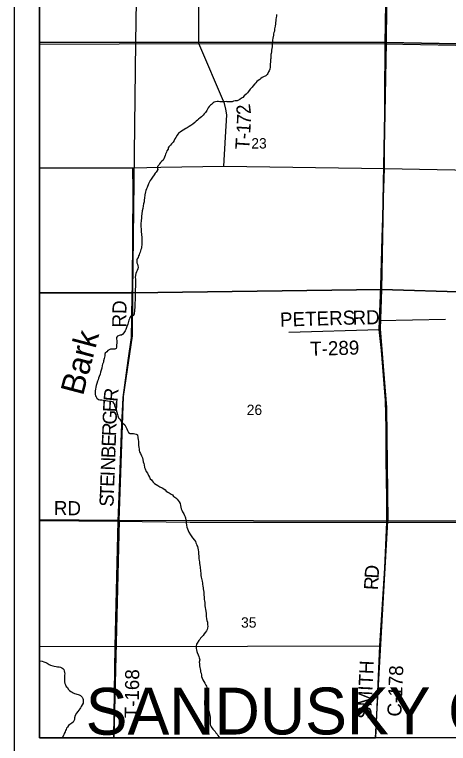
# Model space of a CAD drawing. Extents: x 0 to 34, y 0 to 22.
# Drawn here: x 23.417 to 25.169, y 14.078 to 17.024 of the extents above; entities that cross this region are included whole.
import ezdxf

# ---------------------------------------------------------------- set-up
doc = ezdxf.new("R2010")
doc.units = 0
for name, color, linetype in [('GM_X_County_Road', 7, 'Continuous'), ('GM_X_County_Road_Text', 7, 'Continuous'), ('GM_X_County_Text', 7, 'Continuous'), ('GM_X_Minor_River', 7, 'Continuous'), ('GM_X_Minor_River_Text', 7, 'Continuous'), ('GM_X_Section', 7, 'Continuous'), ('GM_X_Section_Text', 7, 'Continuous'), ('GM_X_Township_Road', 7, 'Continuous'), ('GM_X_Township_Road_Text', 7, 'Continuous'), ('SH_Data', 7, 'Continuous')]:
    doc.layers.add(name, color=color, linetype=linetype)

msp = doc.modelspace()

# ---------------------------------------------------------------- linework, layer by layer
at = {"layer": 'GM_X_County_Road'}
msp.add_line((23.5167, 14.9786), (23.8356, 14.976), dxfattribs=at)
for points in [[(24.9139, 16.9052), (24.9179, 17.1535), (24.9168, 17.4836), (24.9237, 17.8223), (24.9385, 18.1961), (24.9527, 18.4155)], [(24.9115, 16.4019), (24.9123, 16.6864), (24.9139, 16.9052)], [(24.007, 16.4066), (24.2617, 16.4112), (24.9115, 16.4019), (25.9746, 16.3822)], [(23.5167, 16.4046), (23.8475, 16.4049), (23.8949, 16.4045), (24.007, 16.4066)], [(24.9205, 14.9723), (24.9198, 15.0684), (24.9178, 15.2261), (24.9171, 15.3511), (24.9151, 15.464), (24.8982, 15.6659), (24.8893, 15.7512), (24.8908, 15.788), (24.8963, 15.9243), (24.901, 16.1233), (24.9115, 16.4019)], [(23.8356, 14.976), (24.1256, 14.9725), (24.4361, 14.9725), (24.6013, 14.9725), (24.9205, 14.9723), (25.4304, 14.971), (25.8247, 14.9796), (25.8949, 14.9801), (25.9099, 14.9816), (25.9117, 14.9818), (25.9196, 14.987)], [(24.8753, 14.1), (24.892, 14.4729), (24.9118, 14.7856), (24.9205, 14.9723)]]:
    msp.add_lwpolyline(points, dxfattribs=at)
at = {"layer": 'GM_X_Minor_River'}
for points in [[(24.475, 17.0244), (24.4742, 17.0179), (24.4734, 17.0122), (24.4725, 17.0035), (24.4721, 16.9982), (24.4709, 16.9918), (24.47, 16.9861), (24.4692, 16.9774), (24.4676, 16.9721), (24.4672, 16.9668), (24.4659, 16.9569), (24.4643, 16.952), (24.4631, 16.9459), (24.4619, 16.941), (24.4603, 16.9281), (24.4587, 16.9209), (24.4578, 16.9156), (24.4574, 16.908), (24.4569, 16.9031), (24.4569, 16.8986), (24.4565, 16.8936), (24.4556, 16.8864), (24.4548, 16.88), (24.454, 16.8732), (24.4531, 16.8671), (24.4523, 16.8622), (24.4522, 16.8538), (24.4514, 16.847), (24.4509, 16.8417), (24.4504, 16.8311), (24.4496, 16.8254), (24.4491, 16.8163), (24.4487, 16.811), (24.4475, 16.8034), (24.4451, 16.797), (24.4428, 16.792), (24.4397, 16.7864)], [(24.4397, 16.7864), (24.4366, 16.7815), (24.4312, 16.777), (24.4225, 16.7721), (24.4171, 16.7695), (24.4118, 16.7654), (24.4068, 16.7617), (24.4011, 16.7579), (24.3957, 16.7531), (24.3907, 16.7482), (24.3869, 16.7437), (24.3792, 16.735), (24.3761, 16.7301), (24.3684, 16.7219), (24.3615, 16.7128), (24.3572, 16.7079), (24.3515, 16.7019), (24.3442, 16.6952), (24.3381, 16.6892), (24.3335, 16.6862), (24.3266, 16.6802), (24.3212, 16.6776), (24.3159, 16.6757), (24.3072, 16.6747), (24.3007, 16.674), (24.2958, 16.6718), (24.2901, 16.6714), (24.2817, 16.6712), (24.2756, 16.6712), (24.2707, 16.672), (24.2582, 16.6718), (24.251, 16.6715), (24.2461, 16.6715), (24.2408, 16.6724), (24.2351, 16.672), (24.2279, 16.6714), (24.2229, 16.6703), (24.2183, 16.6669), (24.2125, 16.6598), (24.208, 16.6575), (24.203, 16.6523), (24.1991, 16.6466), (24.1937, 16.6364), (24.1872, 16.6285), (24.1818, 16.6225), (24.1779, 16.6176), (24.1722, 16.6112), (24.1664, 16.6063), (24.1599, 16.6011), (24.1553, 16.597), (24.15, 16.5925), (24.1442, 16.5872), (24.1365, 16.5805), (24.1285, 16.5756), (24.122, 16.5715), (24.114, 16.5655), (24.109, 16.5633), (24.0976, 16.5566), (24.0915, 16.5529), (24.085, 16.5488), (24.0804, 16.5465), (24.0765, 16.5409), (24.0738, 16.5364), (24.0684, 16.5277), (24.0646, 16.5213), (24.0614, 16.5148), (24.0576, 16.5084), (24.0503, 16.5017), (24.0461, 16.4964), (24.0399, 16.49), (24.0376, 16.4847), (24.0368, 16.4798), (24.0321, 16.473), (24.0302, 16.4681), (24.0263, 16.4598), (24.0251, 16.4549), (24.0224, 16.4473), (24.02, 16.4413), (24.0162, 16.4352), (24.0116, 16.4315), (24.0062, 16.4255), (24.0016, 16.421), (23.9989, 16.4153), (23.9946, 16.4104), (23.9938, 16.4024), (23.9956, 16.3971), (23.9914, 16.3915), (23.9883, 16.3869), (23.9845, 16.3824), (23.9806, 16.3764), (23.9733, 16.367), (23.969, 16.3591), (23.9644, 16.353), (23.9613, 16.3481), (23.9574, 16.3398), (23.9523, 16.3251), (23.9496, 16.3194), (23.9473, 16.3126), (23.9457, 16.3069), (23.9433, 16.2956), (23.9432, 16.291)], [(23.9432, 16.291), (23.942, 16.2865), (23.9407, 16.2717), (23.9395, 16.2668), (23.9379, 16.2592), (23.9363, 16.2512), (23.9343, 16.2406), (23.9323, 16.2304), (23.9306, 16.2186), (23.9294, 16.2088), (23.9289, 16.2038), (23.9284, 16.1894), (23.9272, 16.1807), (23.9267, 16.1705), (23.9266, 16.1659), (23.9273, 16.1576), (23.9276, 16.153), (23.9279, 16.1446), (23.929, 16.1378), (23.9297, 16.1325), (23.9303, 16.126), (23.931, 16.1165), (23.9313, 16.1101), (23.9312, 16.0991), (23.9307, 16.0937), (23.9299, 16.0858), (23.9287, 16.0797), (23.9267, 16.074), (23.9255, 16.0695), (23.9236, 16.0635), (23.9216, 16.0582), (23.92, 16.0529), (23.9173, 16.0483), (23.9153, 16.0415), (23.9123, 16.0366), (23.9107, 16.0321), (23.9099, 16.0275), (23.9109, 16.0199), (23.9131, 16.015), (23.9146, 16.0085), (23.9153, 16.0024), (23.9148, 15.9967), (23.9113, 15.9892), (23.9086, 15.9843), (23.907, 15.9771), (23.9047, 15.9706), (23.9038, 15.9615), (23.9045, 15.9558), (23.9056, 15.9494), (23.9051, 15.9399), (23.905, 15.935), (23.9054, 15.93), (23.9045, 15.9221), (23.9044, 15.9152), (23.904, 15.9099), (23.9043, 15.9019), (23.9041, 15.8883), (23.9036, 15.8792), (23.9032, 15.8697), (23.903, 15.8591), (23.9026, 15.8503), (23.9025, 15.8458), (23.902, 15.839), (23.9012, 15.8314), (23.9007, 15.8242), (23.9003, 15.8185), (23.8999, 15.8139), (23.8975, 15.8071), (23.8914, 15.8049), (23.8869, 15.8049), (23.8826, 15.8001), (23.8814, 15.7944), (23.8783, 15.7891), (23.8768, 15.7838), (23.8756, 15.7777), (23.8736, 15.7728), (23.8705, 15.7637), (23.8693, 15.7592), (23.8654, 15.7505), (23.8631, 15.7456), (23.8576, 15.7369), (23.8534, 15.732), (23.8488, 15.7287), (23.8435, 15.728), (23.8389, 15.7269), (23.8325, 15.7235), (23.8286, 15.719), (23.8285, 15.7126), (23.83, 15.705), (23.8299, 15.7004), (23.8282, 15.6845), (23.8278, 15.6795), (23.8266, 15.6739), (23.8212, 15.6716), (23.814, 15.6713), (23.8091, 15.6718), (23.8042, 15.6711), (23.7985, 15.6688), (23.7935, 15.6662), (23.7893, 15.661), (23.7831, 15.6557)], [(23.7831, 15.6557), (23.7808, 15.6512), (23.7807, 15.6444), (23.7799, 15.6387), (23.7791, 15.6338), (23.7763, 15.6239), (23.7755, 15.6186), (23.7724, 15.6107), (23.7704, 15.6054), (23.7688, 15.5951), (23.7656, 15.583), (23.7641, 15.5785), (23.7617, 15.5705), (23.7585, 15.5607), (23.7562, 15.5539), (23.7538, 15.5475), (23.7519, 15.5418), (23.7487, 15.5331), (23.746, 15.5244), (23.7444, 15.5176), (23.7432, 15.5104), (23.7423, 15.5024), (23.7415, 15.4952), (23.7418, 15.4888), (23.7436, 15.483), (23.7459, 15.4785), (23.7485, 15.4739), (23.756, 15.4681), (23.7616, 15.4669), (23.7692, 15.4664), (23.7738, 15.4649), (23.7794, 15.4644), (23.7848, 15.464), (23.7919, 15.4624), (23.8003, 15.4616), (23.8067, 15.4607), (23.812, 15.4595), (23.8161, 15.453), (23.8199, 15.4481), (23.8209, 15.442), (23.8224, 15.4366), (23.8264, 15.4256), (23.8301, 15.4164), (23.8323, 15.4077), (23.8337, 15.4024), (23.8367, 15.3944), (23.8412, 15.3879), (23.8479, 15.3772), (23.8543, 15.3718), (23.8614, 15.3656), (23.8659, 15.3576), (23.8696, 15.3496), (23.8729, 15.3423), (23.8774, 15.3351), (23.8841, 15.3308), (23.891, 15.3308), (23.8974, 15.3303), (23.9027, 15.3291), (23.9073, 15.3283), (23.9125, 15.3252), (23.9151, 15.3138), (23.9153, 15.3054), (23.9172, 15.2997), (23.917, 15.283), (23.9184, 15.2735), (23.9199, 15.269), (23.9202, 15.2617), (23.9216, 15.2568), (23.9257, 15.2495), (23.9294, 15.2408), (23.9338, 15.2316), (23.9349, 15.2255), (23.9363, 15.2164), (23.9385, 15.2092), (23.9404, 15.2038), (23.9421, 15.1932), (23.9447, 15.1875), (23.9484, 15.1772), (23.9533, 15.1703), (23.9581, 15.1607), (23.961, 15.1546), (23.9648, 15.1478), (23.9693, 15.1439), (23.9726, 15.1389), (23.9767, 15.1336), (23.9824, 15.1286), (23.9884, 15.124), (23.9959, 15.1201), (24.0031, 15.1155), (24.0129, 15.1108), (24.0197, 15.1066), (24.0246, 15.1023), (24.0294, 15.0977), (24.0351, 15.0939), (24.0415, 15.0904), (24.0494, 15.0857), (24.0539, 15.0823), (24.0584, 15.0765), (24.0633, 15.0731), (24.0678, 15.0707), (24.0734, 15.0654)], [(24.0734, 15.0654), (24.0772, 15.0596), (24.082, 15.0543), (24.0854, 15.0474), (24.0864, 15.0402), (24.0886, 15.0322), (24.0897, 15.0265), (24.0919, 15.0204), (24.0949, 15.0146), (24.1008, 15.0062), (24.1034, 14.9997), (24.1056, 14.9944), (24.1071, 14.9895), (24.1085, 14.98), (24.1092, 14.9743), (24.1095, 14.9689), (24.1113, 14.9606), (24.1131, 14.9526), (24.115, 14.9457), (24.1175, 14.9381), (24.1209, 14.9312), (24.1272, 14.9205), (24.1358, 14.9083), (24.144, 14.8991), (24.147, 14.8938), (24.1492, 14.8884), (24.151, 14.8838), (24.1529, 14.8781), (24.1551, 14.8735), (24.1569, 14.8674), (24.1576, 14.861), (24.159, 14.8526), (24.1601, 14.8435), (24.1607, 14.8359), (24.1614, 14.8253), (24.1621, 14.8177), (24.1631, 14.8123), (24.1638, 14.8051), (24.1645, 14.7983), (24.1659, 14.7899), (24.1666, 14.7853), (24.1677, 14.7793), (24.168, 14.7736), (24.1687, 14.7667), (24.1686, 14.7622), (24.1693, 14.7572), (24.1708, 14.7496), (24.1725, 14.7397), (24.174, 14.7333), (24.1754, 14.7257), (24.1757, 14.7211), (24.1768, 14.7135), (24.1779, 14.7074), (24.1786, 14.7025), (24.1793, 14.696), (24.1807, 14.6888), (24.1817, 14.6774), (24.1824, 14.6705), (24.1827, 14.6652), (24.183, 14.6595), (24.1841, 14.6538), (24.1848, 14.6474), (24.1851, 14.6405), (24.1858, 14.6356), (24.1868, 14.6265), (24.1879, 14.6207), (24.19, 14.6036), (24.1903, 14.5983), (24.1906, 14.5926), (24.192, 14.582), (24.1934, 14.5748), (24.1953, 14.5679), (24.1956, 14.5626), (24.1959, 14.5576), (24.1966, 14.5519), (24.1957, 14.5432), (24.1942, 14.5379), (24.1918, 14.5334), (24.1876, 14.5277), (24.183, 14.5206), (24.178, 14.5142), (24.173, 14.5082), (24.1676, 14.5029), (24.1645, 14.4984), (24.1607, 14.4939), (24.1537, 14.4837), (24.151, 14.4784), (24.1502, 14.4716), (24.1505, 14.4663), (24.1504, 14.4609), (24.1515, 14.4556), (24.1526, 14.4499), (24.1544, 14.445), (24.1581, 14.4358), (24.1607, 14.4286), (24.1621, 14.4232), (24.1647, 14.4152), (24.1627, 14.4069), (24.1634, 14.3993), (24.1637, 14.3921), (24.1655, 14.3849)], [(23.5167, 14.4122), (23.5198, 14.4119), (23.5274, 14.4099), (23.5342, 14.4083), (23.5425, 14.4052), (23.5478, 14.4017), (23.5557, 14.3974), (23.5613, 14.3947), (23.5712, 14.3912), (23.5772, 14.3896), (23.584, 14.3888), (23.5901, 14.388), (23.5973, 14.3875), (23.6018, 14.3859), (23.6071, 14.3836), (23.6116, 14.3805), (23.6161, 14.3763), (23.6168, 14.3714), (23.6183, 14.3641), (23.619, 14.3592), (23.6189, 14.3531), (23.6181, 14.3478), (23.618, 14.3433), (23.618, 14.3376), (23.6179, 14.3322), (23.6182, 14.3262), (23.6201, 14.3205), (23.6223, 14.3151), (23.6256, 14.3086), (23.6301, 14.3036), (23.6334, 14.2972), (23.6387, 14.2918), (23.6436, 14.2879), (23.6489, 14.2852)], [(24.1655, 14.3849), (24.1658, 14.3788), (24.1672, 14.3731), (24.1683, 14.3678), (24.1702, 14.3613), (24.1712, 14.3537), (24.1719, 14.348), (24.1745, 14.3419), (24.1767, 14.3346), (24.1815, 14.3278), (24.1852, 14.3209), (24.189, 14.3136), (24.1916, 14.3087), (24.193, 14.3033), (24.1945, 14.2969), (24.1948, 14.2908), (24.1947, 14.2847), (24.1935, 14.279), (24.1908, 14.2715), (24.1873, 14.2643), (24.1849, 14.2552), (24.1837, 14.2491), (24.1832, 14.2423), (24.1843, 14.2351), (24.1865, 14.229), (24.1914, 14.2252), (24.1943, 14.2206), (24.1962, 14.2156), (24.2007, 14.2091), (24.2025, 14.2023), (24.205, 14.192), (24.2064, 14.1821), (24.2068, 14.1775), (24.2063, 14.1726), (24.2066, 14.1631), (24.2073, 14.1563), (24.2084, 14.1509), (24.2102, 14.1448), (24.2177, 14.136), (24.2222, 14.1303), (24.2267, 14.1257), (24.23, 14.1207), (24.2345, 14.1146), (24.2375, 14.11), (24.2412, 14.1047), (24.2442, 14.1)], [(23.6489, 14.2852), (23.6538, 14.2821), (23.6591, 14.2802), (23.664, 14.2786), (23.6685, 14.2774), (23.673, 14.2762), (23.6776, 14.2747), (23.6832, 14.2719), (23.6892, 14.2643), (23.6926, 14.2597), (23.6933, 14.2548), (23.694, 14.2472), (23.6935, 14.24), (23.69, 14.2339), (23.6861, 14.2275), (23.6827, 14.2222), (23.68, 14.2177), (23.6761, 14.2124), (23.6719, 14.2075), (23.6661, 14.2004), (23.6618, 14.1913), (23.6591, 14.1807), (23.6586, 14.1747), (23.6563, 14.1686), (23.6528, 14.1633), (23.6474, 14.16), (23.6398, 14.1544), (23.6348, 14.1502), (23.6298, 14.1438), (23.6267, 14.1393), (23.6244, 14.1344), (23.6224, 14.1299), (23.6205, 14.1249), (23.6166, 14.1178), (23.6154, 14.1121), (23.61, 14.1038), (23.6081, 14.1)]]:
    msp.add_lwpolyline(points, dxfattribs=at)
at = {"layer": 'GM_X_Section'}
for points in [[(23.5167, 17.9073), (23.5167, 16.9109), (23.906, 16.9126), (23.9224, 17.9096)], [(24.9267, 17.9117), (24.9171, 16.9109), (23.906, 16.9126), (23.9224, 17.9096)], [(26.0158, 17.891), (25.9875, 16.9239), (25.9861, 16.8906), (24.9171, 16.9109), (24.9267, 17.9117)], [(23.5167, 16.9109), (23.5167, 15.8988), (23.8944, 15.8992), (23.906, 16.9126)], [(24.9171, 16.9109), (24.8984, 15.9127), (23.8944, 15.8992), (23.906, 16.9126)], [(25.9861, 16.8906), (25.9635, 15.9304), (25.9617, 15.8807), (24.8984, 15.9127), (24.9171, 16.9109)], [(24.8984, 15.9127), (24.894, 15.7536), (24.9186, 15.4351), (24.9245, 14.9768), (23.8391, 14.9794), (23.8562, 15.4795), (23.893, 15.7257), (23.8944, 15.8992)], [(25.9617, 15.8807), (25.9137, 14.9847), (25.9129, 14.9756), (24.9245, 14.9768), (24.9186, 15.4351), (24.894, 15.7536), (24.8984, 15.9127)], [(23.5167, 15.8988), (23.5167, 14.9817), (23.8391, 14.9794), (23.8562, 15.4795), (23.893, 15.7257), (23.8944, 15.8992)], [(23.5167, 14.9817), (23.5167, 14.1), (23.8171, 14.1), (23.8391, 14.9794)], [(23.8171, 14.1), (24.8743, 14.1), (24.9245, 14.9768), (23.8391, 14.9794)]]:
    msp.add_lwpolyline(points, close=True, dxfattribs=at)
at = {"layer": 'GM_X_Township_Road'}
for p, q in [((24.1604, 16.9066), (24.1639, 17.9096)), ((23.5167, 16.9042), (24.1604, 16.9066)), ((23.8905, 15.7964), (23.8908, 15.816)), ((24.8908, 15.788), (25.1574, 15.7929)), ((24.524, 15.7407), (24.8893, 15.7512))]:
    msp.add_line(p, q, dxfattribs=at)
for points in [[(24.2617, 16.4112), (24.2682, 16.5285), (24.2746, 16.6184), (24.2704, 16.642), (24.265, 16.6645), (24.1604, 16.9066)], [(24.1604, 16.9066), (24.9139, 16.9052), (25.9854, 16.8861)], [(23.8908, 15.816), (23.8928, 15.9385), (23.8957, 16.3126), (23.8949, 16.4045)], [(23.8356, 14.976), (23.8404, 15.1104), (23.8502, 15.3686), (23.8546, 15.4764), (23.8756, 15.6261), (23.8892, 15.7189), (23.8905, 15.7964)], [(23.8182, 14.1), (23.8226, 14.4702), (23.8356, 14.976)], [(23.5167, 14.4709), (23.8226, 14.4702), (24.892, 14.4729)]]:
    msp.add_lwpolyline(points, dxfattribs=at)
at = {"layer": 'SH_Data'}
for points in [[(23.4167, 21), (30.4167, 21), (30.4167, 14), (23.4167, 14)], [(23.5167, 20.9), (30.3167, 20.9), (30.3167, 14.1), (23.5167, 14.1)]]:
    msp.add_lwpolyline(points, close=True, dxfattribs=at)

# ---------------------------------------------------------------- texts
at = {"layer": 'GM_X_County_Road_Text'}
for s, height, rotation, p in [('RD', 0.05682, 359.5063, (23.5751, 15.001)), ('D', 0.0568, 86.4825, (24.8868, 14.7431)), ('R', 0.0568, 86.8175, (24.8842, 14.6966)), ('SMITH', 0.05682, 87.347, (24.8567, 14.1755)), ('C-178', 0.05682, 87.5227, (24.9785, 14.1852))]:
    msp.add_text(s, height=height, rotation=rotation, dxfattribs=at).set_placement(p)
at = {"layer": 'GM_X_County_Text'}
msp.add_text('SANDUSKY COUNTY', height=0.189394, rotation=0.0833, dxfattribs=at).set_placement((23.7039, 14.1129))
at = {"layer": 'GM_X_Minor_River_Text'}
msp.add_text('Bark', height=0.09475, rotation=75.2004, dxfattribs=at).set_placement((23.6925, 15.4803))
at = {"layer": 'GM_X_Section_Text'}
for s, p in [('23', (24.3728, 16.4825)), ('26', (24.3544, 15.4054)), ('35', (24.3315, 14.5458))]:
    msp.add_text(s, height=0.04186, rotation=0, dxfattribs=at).set_placement(p)
at = {"layer": 'GM_X_Township_Road_Text'}
for s, height, rotation, p in [('2', 0.0568, 96.5328, (24.3719, 16.623)), ('7', 0.0568, 87.5149, (24.3707, 16.5783)), ('1', 0.0568, 86.4772, (24.3685, 16.5422)), ('-', 0.0568, 86.2227, (24.367, 16.5187)), ('T', 0.0568, 86.1443, (24.3641, 16.4762)), ('RD', 0.05682, 89.0303, (23.8675, 15.7584)), ('PETERS', 0.05682, 1.6433, (24.4896, 15.7625)), ('RD', 0.05682, 1.6433, (24.7824, 15.7699)), ('T-289', 0.05682, 1.6433, (24.6114, 15.6443)), ('R', 0.0568, 84.5236, (23.832, 15.4574)), ('E', 0.0568, 87.5822, (23.8302, 15.4157)), ('G', 0.0568, 87.843, (23.8284, 15.3658)), ('R', 0.0568, 87.845, (23.8266, 15.3192)), ('E', 0.0568, 87.8475, (23.825, 15.2767)), ('B', 0.0568, 87.8411, (23.8233, 15.2301)), ('N', 0.0568, 87.8466, (23.8214, 15.1801)), ('I', 0.0568, 87.8467, (23.8205, 15.1568)), ('E', 0.0568, 87.8446, (23.8189, 15.1143)), ('T', 0.0568, 87.8438, (23.8173, 15.0719)), ('S', 0.0568, 87.8471, (23.8159, 15.0335)), ('T-168', 0.05682, 89.1579, (23.9176, 14.1789))]:
    msp.add_text(s, height=height, rotation=rotation, dxfattribs=at).set_placement(p)

doc.saveas('drawing.dxf')
